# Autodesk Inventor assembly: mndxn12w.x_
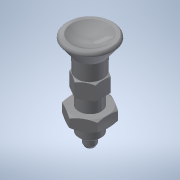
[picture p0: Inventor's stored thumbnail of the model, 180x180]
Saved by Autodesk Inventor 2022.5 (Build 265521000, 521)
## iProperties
Part Number: mndxn12w.x_
Material: 一般
Document SubType Name: Assembly
Designer: ImaoCorp
Sending System: SOLIDWORKS 2017-2017317
MC: AMD64
MC_MODEL: Intel64 Family 6 Model 60 Stepping 3, GenuineIntel
OS: Windows_NT
FRU: Parasolid Version 29.0, build 201,  4-17-2017
FORMAT: text
GUISE: transmit
KEY: mndxn12w
FILE: mndxn12w.x_t
DATE: Fri Jul 26 11:48:09 2019
Author: ImaoCorp
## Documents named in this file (3)
- X:\14_SW2022-Inv2022\00_全2023-1023新製品(TCC)まで\m\mndxn12w\MNDXN12W.iam
- X:\14_SW2022-Inv2022\00_全2023-1023新製品(TCC)まで\m\mndxn12w\mndxn12w_01.ipt
- X:\14_SW2022-Inv2022\00_全2023-1023新製品(TCC)まで\m\mndxn12w\mndxn12w_02.ipt
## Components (2 placed, 2 different names)
1. mndxn12w_01
2. mndxn12w_02
